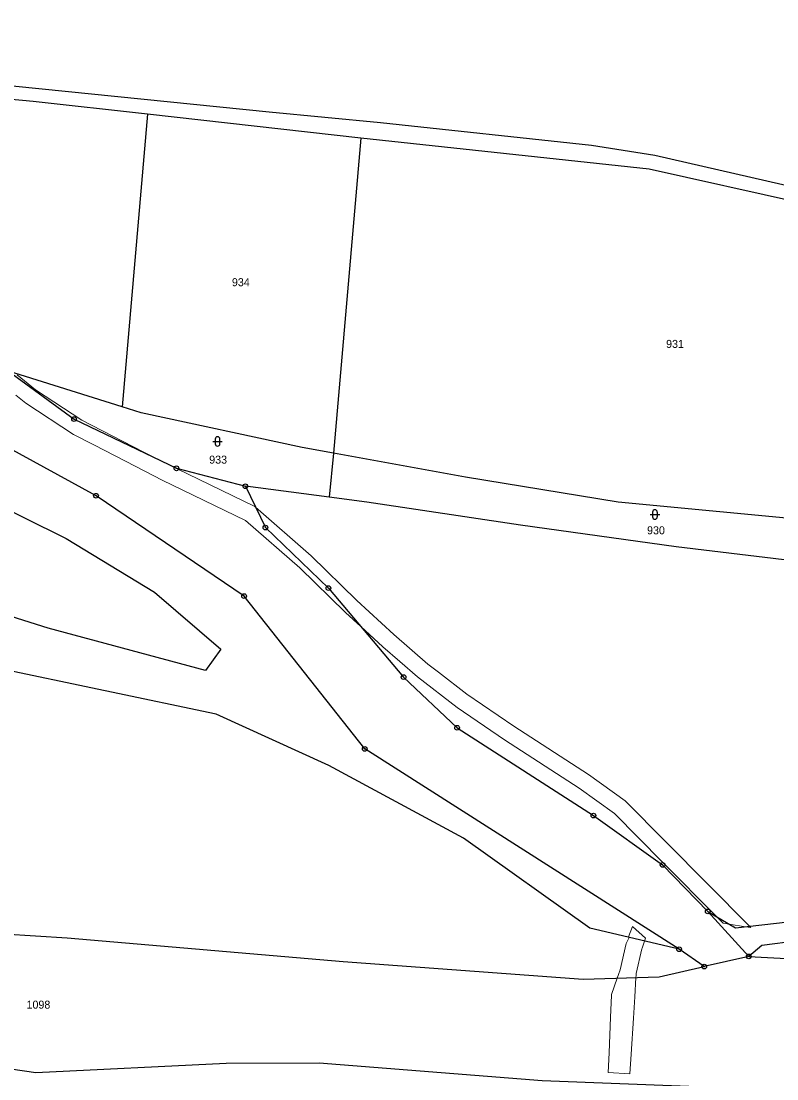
# Model space of a CAD drawing. Extents: x -758887 to -754328, y -1031688 to -1029144.
# Drawn here: x -756999.4 to -756838.8, y -1029651.7 to -1029426.9 of the extents above; entities that cross this region are included whole.
import ezdxf
from ezdxf.enums import TextEntityAlignment as Align

# ---------------------------------------------------------------- set-up
doc = ezdxf.new("R2010")
doc.units = 0
doc.header["$LTSCALE"] = 0.68
for name, color, linetype, lineweight in [('1', 7, 'Continuous', 25), ('13', 7, 'Continuous', 13), ('3', 7, 'Continuous', 25), ('8', 7, 'Continuous', 25)]:
    doc.layers.add(name, color=color, linetype=linetype, lineweight=lineweight)
doc.layers.add('2', color=7, linetype='Continuous')

msp = doc.modelspace()

# ---------------------------------------------------------------- linework, layer by layer
at = {"layer": '1'}
for p, q in [((-756933.9, -1029528.11), (-756951.73, -1029525.77)), ((-756844.75, -1029625.66), (-756853.46, -1029616.12)), ((-756854.23, -1029627.82), (-756859.56, -1029624.13)), ((-756844.75, -1029625.66), (-756854.23, -1029627.82))]:
    msp.add_line(p, q, dxfattribs=at)
for points in [[(-757143.59, -1029426.95), (-757000.54, -1029440.74), (-756946.71, -1029446.19)], [(-756972.53, -1029446.72), (-756996.8, -1029443.99), (-757105.63, -1029433.9), (-757110.21, -1029435.61), (-757110.36, -1029437.91)], [(-756927.21, -1029451.82), (-756972.53, -1029446.72), (-756977.93, -1029508.88)], [(-756946.71, -1029446.19), (-756922.99, -1029448.49), (-756878.16, -1029453.27), (-756864.7, -1029455.42), (-756796.69, -1029471.04), (-756681.08, -1029505.55), (-756677.94, -1029492.24)], [(-756787.78, -1029477.02), (-756801.18, -1029472.88), (-756865.96, -1029458.4), (-756927.21, -1029451.82), (-756933.02, -1029518.73)], [(-757034.58, -1029499.84), (-757021.6, -1029518.44), (-757017.17, -1029523.34), (-756989.85, -1029536.9), (-756971.03, -1029548.24), (-756956.93, -1029560.36), (-756960.24, -1029564.93), (-756993.65, -1029555.93), (-757021.76, -1029547.07), (-757050.12, -1029534.92), (-757111.37, -1029514.33), (-757149.95, -1029510.62), (-757183.23, -1029507.03), (-757211.07, -1029502.14), (-757219.61, -1029496.51), (-757216.56, -1029479.58)], [(-756859.56, -1029624.13), (-756926.38, -1029581.59), (-756952.01, -1029549.12), (-756983.48, -1029527.78), (-757034.58, -1029499.84)], [(-756933.02, -1029518.73), (-756939.65, -1029517.52), (-756973.86, -1029510.15), (-756977.93, -1029508.88), (-757002.1, -1029501.33)], [(-757002.1, -1029501.33), (-756988.14, -1029511.49), (-756966.39, -1029521.96), (-756951.73, -1029525.77)], [(-756859.56, -1029624.13), (-756878.5, -1029619.66), (-756905.38, -1029600.55), (-756934.02, -1029585.08), (-756957.96, -1029574.23), (-757005.2, -1029564.26), (-757029.41, -1029552.16), (-757083.07, -1029533.87), (-757120.35, -1029524.85), (-757152.6, -1029520.72), (-757179.08, -1029518.16), (-757211.51, -1029513.46), (-757239.88, -1029513.02)], [(-756794.86, -1029536.88), (-756806.19, -1029535.43), (-756872.51, -1029529.13), (-756904.96, -1029523.87), (-756933.02, -1029518.73), (-756933.9, -1029528.11)], [(-756951.73, -1029525.77), (-756947.46, -1029534.56), (-756934.09, -1029547.41), (-756918.12, -1029566.32), (-756906.74, -1029577.09), (-756877.78, -1029595.74), (-756863.06, -1029606.21), (-756853.46, -1029616.12)], [(-756795.34, -1029546.92), (-756827.83, -1029542.53), (-756860.19, -1029538.61), (-756893.25, -1029534.07), (-756925.94, -1029529.16), (-756933.9, -1029528.11)], [(-757277.31, -1029597.89), (-757243.97, -1029603.57), (-757212.59, -1029607.57), (-757174.69, -1029611.67), (-757142.99, -1029613.95), (-757109.82, -1029616.21), (-757076.36, -1029618.22), (-757041.86, -1029618.63), (-757009.86, -1029620.47), (-756989.63, -1029621.7), (-756930.92, -1029626.76), (-756879.95, -1029630.51), (-756863.82, -1029630.01), (-756854.23, -1029627.82)], [(-756853.46, -1029616.12), (-756847.58, -1029619.6), (-756828.29, -1029617.39), (-756815.78, -1029617.73), (-756789.21, -1029620.52), (-756741.1, -1029628.39)], [(-756802.89, -1029623.39), (-756806.75, -1029622.2), (-756816.51, -1029620.79), (-756834.29, -1029622.37), (-756841.98, -1029623.32), (-756844.75, -1029625.66)], [(-756844.75, -1029625.66), (-756811.62, -1029627.46), (-756803, -1029633.25)], [(-756857.49, -1029653.28), (-756888.68, -1029652.07), (-756936.06, -1029648.37), (-756955.79, -1029648.43), (-756996.27, -1029650.41), (-757034.99, -1029644.77), (-757072.79, -1029641.54), (-757092.75, -1029640.46), (-757127.36, -1029639.96), (-757155.18, -1029639.23), (-757178.97, -1029637.59), (-757211.55, -1029634.89), (-757246.63, -1029632.37), (-757279.49, -1029631.19), (-757315.6, -1029632.63)]]:
    msp.add_lwpolyline(points, dxfattribs=at)
at = {"layer": '13'}
msp.add_lwpolyline([(-757000.52, -1029506.4), (-756998.39, -1029508.1), (-756988.28, -1029514.75), (-756983.96, -1029516.97), (-756975, -1029521.59), (-756969.43, -1029524.46), (-756951.68, -1029533.02), (-756940.15, -1029543.1), (-756930.45, -1029552.56), (-756927.22, -1029555.55), (-756934.09, -1029547.41), (-756947.46, -1029534.56), (-756949.56, -1029530.24), (-756949.74, -1029530.08), (-756964.07, -1029523.16), (-756967.87, -1029521.32), (-756970.13, -1029520.16), (-756973.46, -1029518.45), (-756986.52, -1029511.73), (-756996.33, -1029505.26), (-757000.26, -1029502.12)], dxfattribs=at)
for points in [[(-756949.56, -1029530.24), (-756947.46, -1029534.56), (-756934.09, -1029547.41), (-756927.22, -1029555.55), (-756922.52, -1029559.89), (-756918.89, -1029563.04), (-756915.17, -1029566.27), (-756906.71, -1029572.79), (-756896.64, -1029579.65), (-756880.78, -1029589.95), (-756873.31, -1029595.31), (-756863.08, -1029605.62), (-756851.52, -1029617.27), (-756848.89, -1029618.82), (-756845.48, -1029619.36), (-756844.62, -1029619.26), (-756862.38, -1029601.35), (-756871.03, -1029592.63), (-756878.8, -1029587.05), (-756894.7, -1029576.73), (-756904.65, -1029569.95), (-756910.69, -1029565.3), (-756912.95, -1029563.55), (-756920.18, -1029557.29), (-756928.03, -1029550.02), (-756937.77, -1029540.52)], [(-756848.89, -1029618.82), (-756851.52, -1029617.27), (-756850.18, -1029618.62)], [(-756866.67, -1029621.79), (-756869.47, -1029619.28), (-756870.3, -1029621.52), (-756870.19, -1029621.62), (-756870.8, -1029622.89), (-756872.11, -1029628.52), (-756872.46, -1029629.54), (-756872.72, -1029630.29), (-756873.91, -1029633.78), (-756873.92, -1029633.98), (-756874.11, -1029638.54), (-756874.43, -1029646.15), (-756874.61, -1029650.35), (-756870, -1029650.58), (-756869.74, -1029646.43), (-756869.27, -1029638.78), (-756868.99, -1029634.27), (-756868.75, -1029630.16), (-756868.72, -1029629.74), (-756868.69, -1029629.32), (-756867.48, -1029624.07), (-756867.44, -1029623.89), (-756866.89, -1029622.4)], [(-756844.62, -1029619.26), (-756845.48, -1029619.36), (-756844.34, -1029619.54)]]:
    msp.add_lwpolyline(points, close=True, dxfattribs=at)
at = {"layer": '3'}
for p, q in [((-756958.661, -1029516.251), (-756956.659, -1029516.251)), ((-756958.161, -1029515.751), (-756958.161, -1029516.752)), ((-756957.159, -1029516.752), (-756957.159, -1029515.751)), ((-756865.691, -1029531.771), (-756863.689, -1029531.771)), ((-756865.191, -1029531.271), (-756865.191, -1029532.272)), ((-756864.189, -1029532.272), (-756864.189, -1029531.271))]:
    msp.add_line(p, q, dxfattribs=at)
for centre, start, end in [((-756957.66, -1029515.7509), 0, 180), ((-756957.66, -1029516.7509), 180, 359.98789), ((-756864.69, -1029531.2709), 0, 180), ((-756864.69, -1029532.2709), 180, 359.98789)]:
    msp.add_arc(centre, 0.5, start, end, dxfattribs=at)
at = {"layer": '8'}
for centre, radius in [((-756988.14, -1029511.4899), 0.5), ((-756988.14, -1029511.4899), 0.0303), ((-756966.39, -1029521.9599), 0.5), ((-756966.39, -1029521.9599), 0.0303), ((-756951.73, -1029525.7699), 0.5), ((-756951.73, -1029525.7699), 0.0303), ((-756983.48, -1029527.7799), 0.5), ((-756983.48, -1029527.7799), 0.0303), ((-756947.46, -1029534.5599), 0.5), ((-756947.46, -1029534.5599), 0.0303), ((-756934.09, -1029547.4099), 0.5), ((-756934.09, -1029547.4099), 0.0303), ((-756952.01, -1029549.1199), 0.5), ((-756952.01, -1029549.1199), 0.0303), ((-756918.12, -1029566.3199), 0.5), ((-756918.12, -1029566.3199), 0.0303), ((-756906.74, -1029577.0899), 0.5), ((-756906.74, -1029577.0899), 0.0303), ((-756926.38, -1029581.5899), 0.5), ((-756926.38, -1029581.5899), 0.0303), ((-756877.78, -1029595.7399), 0.5), ((-756877.78, -1029595.7399), 0.0303), ((-756863.06, -1029606.2099), 0.5), ((-756863.06, -1029606.2099), 0.0303), ((-756853.46, -1029616.1199), 0.5), ((-756853.46, -1029616.1199), 0.0303), ((-756859.56, -1029624.1299), 0.5), ((-756859.56, -1029624.1299), 0.0303), ((-756844.75, -1029625.6599), 0.5), ((-756844.75, -1029625.6599), 0.0303), ((-756854.23, -1029627.8199), 0.5), ((-756854.23, -1029627.8199), 0.0303)]:
    msp.add_circle(centre, radius, dxfattribs=at)

# ---------------------------------------------------------------- texts
at = {"layer": '2'}
for s, p in [('934', (-756952.699, -1029483.266)), ('931', (-756860.429, -1029496.376)), ('933', (-756957.529, -1029520.966)), ('930', (-756864.479, -1029535.976)), ('1098', (-756995.72, -1029636.766))]:
    msp.add_text(s, height=1.7, dxfattribs=at).set_placement(p, align=Align.CENTER)

doc.saveas('drawing.dxf')
